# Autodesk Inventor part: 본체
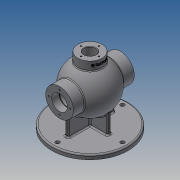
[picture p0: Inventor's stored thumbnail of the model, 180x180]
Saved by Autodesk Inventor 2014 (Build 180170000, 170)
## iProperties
Created: 2020-08
Part Number: 본체
Material: Generic
Document SubType Name: Modeling
Designer: kb542-5
Density: 1 g/cm^3
Appearance: Default
Author: kb542-5
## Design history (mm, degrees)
revolve "회전4" stored, may be unused: angle "d34" = 90 deg
node "작업 평면1"
revolve "회전5" stored, may be unused: angle "d35" = 90 deg
sketch "스케치2"
  geometry: L1 (-68, -31)-(68, -31) reference; L2 (-68, 31)-(68, 31) reference; L3 (-68, -31)-(-68, 31) reference; C1 r 85 at (0, 0); 2 further points; 1 other entity
  constraints: 1 centre point, 1 coincident, 1 other
  dimensions: "d5" = 170 diameter of C1
extrude "돌출1" join sketch "스케치2" distance "d6" = 10; taper "d7" = 0 deg
revolve "회전3" stored, may be unused: angle "d20" = 90 deg
node "작업 평면2"
sketch "스케치5"
  geometry: C1 r 27 at (0, 0); 1 further point
  constraints: 1 centre point, 1 coincident
  dimensions: "d22" = 54 diameter of C1
extrude "돌출3" join sketch "스케치5" stored distance "d23" = 10; taper "d24" = 0 deg
sketch "스케치6"
  geometry: 1 further point
sketch "스케치8"
  geometry: C1 r 31 at (0, 0) reference; C2 r 17.5 at (0, 0) reference
hole "구멍1" diameter "d38" = 26; stored, may be unused: countersink angle "d42" = 90 deg, drill point angle "d44" = 0 deg; dims "d36" = 10, "d37" = 10, "d39" = 6, "d40" = 4, "d41" = 2, "d43" = 8
sketch "스케치9"
  geometry: C1 r 13 at (0, 0) reference; 1 further point
  constraints: 1 vertical alignment
  dimensions: "d45" = 20 distance of point (0, 20) C1.centre
hole "구멍2" sketch "스케치9" at (0, 20) diameter "d46" = 3.242; stored, may be unused: countersink angle "d50" = 90 deg, drill point angle "d52" = 118 deg; dims "d47" = 12, "d48" = 4, "d49" = 2, "d51" = 15
sketch "스케치10"
  geometry: C1 r 17.5 at (0, 0) reference; 1 further point
  constraints: 1 horizontal alignment
  dimensions: "d56" = 24 distance of C1.centre point (-24, 0)
hole "구멍3" sketch "스케치10" at (-24, 0) diameter "d57" = 3.242; stored, may be unused: countersink angle "d61" = 90 deg, drill point angle "d63" = 118 deg; dims "d58" = 12, "d59" = 4, "d60" = 2, "d62" = 15
sketch "스케치3"
  geometry: L1 (-4, 43)-(4, 43); L2 (4, -43)-(-4, -43); L3 (-52, 4)-(52, 4); L4 (52, 4)-(52, -4); L5 (52, -4)-(-52, -4); L6 (-52, -4)-(-52, 4); L7 (-4, 43)-(-4, -43); L8 (4, 43)-(4, -43); C1 r 85 at (0, 0) reference; 5 further points
  constraints: 16 end point, 5 parallel, 4 midpoint, 3 horizontal alignment, 3 vertical alignment, 2 horizontal, 1 perpendicular
  dimensions: "d8" = 8 distance of L5.end L3.start; "d9" = 8 distance of L1.start L1.end; "d10" = 104 distance of L3.start L3.end; "d95" = 86 distance of L2.start L1.end
extrude "돌출4" join sketch "스케치3" stored distance "d67" = 10; taper "d68" = 0 deg
sketch "스케치11"
  geometry: C1 r 85 at (0, 0) reference; 1 further point
  constraints: 1 vertical alignment
  dimensions: "d69" = 72.5 distance of C1.centre point (0, 72.5)
hole "구멍4" sketch "스케치11" at (0, 72.5) diameter "d70" = 9; stored, may be unused: countersink angle "d74" = 90 deg, drill point angle "d76" = 118 deg; dims "d71" = 12, "d72" = 4, "d73" = 2, "d75" = 15
fillet "모깎기1" dims "d80" = 3
fillet "모깎기2" dims "d81" = 3
feature "결합1"
  node "솔리드1"
fillet "모깎기3" dims "d82" = 3
chamfer "모따기1" distance "d83" = 1; stored, may be unused: second distance "d84" = 2, angle "d85" = 45 deg
node "작업 평면3"
sketch "스케치12"
  geometry: L1 (-27, 65)-(27, 65) reference; L2 (-27, 65)-(-27, 47.286) reference; 2 further points
  constraints: 1 other
  dimensions: "d91" = 9 distance from line of point (0, 56) L1; "d92" = 27 distance from line of L2 point (0, 56)
feature "엠보싱1" sketch "스케치12" dims "d0" = 62, "d8" = 8, "d9" = 8, "d10" = 104, "d18" = 106, "d19" = 86, "d27" = 13.5, "d32" = 136, "d33" = 68, "d86" = 16, "d87" = 37, "d88" = 1.75, "d89" = 35, "d93" = 0.5, "d94" = 0, "d95" = 86
sketch "스케치13"
  geometry: C1 r 17.5 at (0, 0) reference
extrude "돌출5" join sketch "스케치13" stored distance "d96" = 10; taper "d97" = 0 deg
extrude "돌출6" join sketch "스케치3" stored distance "d98" = 10; taper "d99" = 0 deg
fillet "모깎기4" dims "d100" = 3
fillet "모깎기5" dims "d101" = 3
sketch "스케치1"
  geometry: L1 (-68, 31)-(-42.988, 31); L2 (68, 31)-(68, 17.5); L3 (-68, 17.5)-(-68, 31); L4 (68, 0)-(-68, 0); L5 (0, 53)-(0, -53); L6 (-50.027, 17.5)-(-39.278, 17.5); L7 (42.988, 31)-(68, 31); L8 (50.027, 17.5)-(68, 17.5); L9 (-42.988, 31)-(42.988, 31); L10 (39.278, 17.5)-(50.027, 17.5); L11 (-39.278, 17.5)-(39.278, 17.5); L12 (-52, 0)-(-50.25, 0); L13 (-50.25, 17.5)-(-50.25, 18.5); L14 (-50.25, 18.5)-(-52, 18.5); L15 (-52, 18.5)-(-52, 17.5); L16 (-68, 17.5)-(-52, 17.5); L17 (-50.25, 17.5)-(-39.278, 17.5); A1 r 53 centre (0, 0) between (0, 53) and (-42.988, 31); A2 r 43 centre (0, 0) between (0, 43) and (-29.799, 31); A3 r 53 centre (0, 0) between (0, -53) and (50.027, 17.5); A4 r 43 centre (0, 0) between (0, -43) and (39.278, 17.5); A5 r 53 centre (0, 0) between (-42.988, 31) and (-50.027, 17.5); A6 r 43 centre (0, 0) between (-29.799, 31) and (-39.278, 17.5); A7 r 43 centre (0, 0) between (-39.278, 17.5) and (0, -43); A8 r 43 centre (0, 0) between (29.799, 31) and (0, 43); A9 r 53 centre (0, 0) between (-50.027, 17.5) and (0, -53); A10 r 43 centre (0, 0) between (39.278, 17.5) and (29.799, 31); A11 r 53 centre (0, 0) between (50.027, 17.5) and (0, 53); 3 further points
  constraints: 34 end point, 24 point on circle, 11 centre point, 10 horizontal, 6 perpendicular, 5 point on line, 3 parallel, 2 coincident, 2 collinear, 2 midpoint, 2 vertical alignment, 2 other
  dimensions: "d0" = 62 diameter of L1 L4; "d18" = 106 diameter of A1; "d19" = 86 diameter of A2; "d27" = 13.5 distance from line of point (0, 31) L8; "d32" = 136 distance between parallel lines of L2 L3; "d33" = 68 distance from line of point (0, 0) L3; "d86" = 16 distance between parallel lines of L15 L3; "d87" = 37 diameter of L14 L4; "d88" = 1.75 distance of L13.end L14.end; "d89" = 35 diameter of L16 L4
pattern_circular "원형 패턴1" dims angle "d54" = 360 deg
pattern_circular "원형 패턴2" dims angle "d65" = 360 deg
mirror "대칭1"
pattern_circular "원형 패턴3" dims angle "d78" = 360 deg
node "솔리드2"
other parameters: "d4" = -85, "d16" = 35, "d90" = -79
